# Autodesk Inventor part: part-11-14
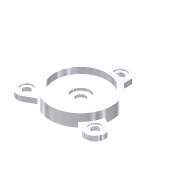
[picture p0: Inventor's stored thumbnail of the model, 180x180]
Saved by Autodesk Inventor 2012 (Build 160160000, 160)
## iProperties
Company: CADCIM Technologies
Shininess: 64.0
Length Units: 11269
Angle Units: 11279
Time Units: 11290
Mass Units: 11283
Length Display Precision: 3
Angle Display Precision: 2
Compacted: True
Part Number: part-11-14
Document SubType Name: Modeling
Created: 2002-12
Designer: deepak
Description: Sample Drawing
Engineer: Deepak
Vendor: CADSoft
Density: 1 g/cm^3
Material: Default
Density: 0.0
Volumn: 0.0
Area: 0.0
PropertySet Name: Model Information
Control State: 0
Master: False
Checked Out: False
Title: Aligned Section
Author: deepak
Revision Number: 4
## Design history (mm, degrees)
node "Sketch1"
sketch "Sketch2"
  geometry: L1 (0, 1)-(0, 5); L2 (0, 5)-(-21.25, 5); L3 (-21.25, 5)-(-21.25, 10); L4 (-21.25, 10)-(-25, 10); L5 (-25, 10)-(-25, 0); L6 (-25, 0)-(-5, 0); L7 (0, 1)-(-5, 1); L8 (-5, 1)-(-5, 0); 1 further point
  constraints: 16 end point, 3 parallel, 3 perpendicular, 1 horizontal, 1 horizontal alignment, 1 vertical, 1 vertical alignment, 1 other
  dimensions: "d0" = 50 diameter of L5 L1; "d1" = 10 diameter of L8 L1; "d2" = 42.5 diameter of L3 L1; "d3" = 10 distance of L4.end L5.end; "d4" = 1 distance of L7.end L6.end; "d5" = 4 distance of L1.start L1.end
revolve "Revolution1" sketch "Sketch2" stored, may be unused: angle "d6" = 90 deg
sketch "Sketch3"
  geometry: C1 r 21.25 at (0, 0) reference
hole "Hole1" sketch "Sketch3" at (0, 0) diameter "d7" = 8; stored, may be unused: countersink angle "d11" = 82 deg, drill point angle "d13" = 118 deg; dims "d8" = 6, "d9" = 15, "d10" = 2, "d12" = 8
sketch "Sketch4"
  geometry: L1 (8, 23.685)-(8, 32); L2 (-8, 32)-(-8, 23.685); C1 r 5 at (0, 0) reference; C2 r 25 at (0, 0) reference; A1 r 8 centre (0, 32) between (8, 32) and (-8, 32); A2 r 25 centre (0, 0) between (8, 23.685) and (-8, 23.685)
  constraints: 4 end point, 4 point on circle, 2 centre point, 2 concentric, 2 tangent, 2 vertical, 1 parallel
  dimensions: "d14" = 8 radius of A1; "d15" = 32 distance of C1.centre A1.centre
extrude "Extrusion1" join sketch "Sketch4" distance "d16" = 4; taper "d17" = 0 deg
sketch "Sketch5"
  geometry: A1 r 8 centre (0, 32) between (8, 32) and (-8, 32) reference
hole "Hole2" sketch "Sketch5" at (0, 32) diameter "d18" = 6; stored, may be unused: countersink angle "d22" = 82 deg, drill point angle "d24" = 118 deg; dims "d19" = 6, "d20" = 10, "d21" = 1, "d23" = 8
pattern_circular "Circular Pattern1" dims angle "d27" = 360 deg
body "Solid1"
